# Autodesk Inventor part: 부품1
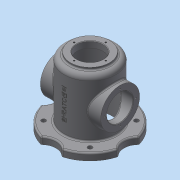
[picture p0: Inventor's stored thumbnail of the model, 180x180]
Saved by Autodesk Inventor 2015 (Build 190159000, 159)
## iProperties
Created: 2022-04
Part Number: 부품1
Material: 일반
Document SubType Name: Modeling
Designer: User
Density: 1 g/cm^3
Appearance: 기본값
Author: User
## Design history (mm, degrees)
sketch "스케치1"
  geometry: C1 r 82 at (0, 0); 1 further point
  constraints: 1 centre point, 1 coincident
  dimensions: "d0" = 164 diameter of C1
extrude "돌출1" new body sketch "스케치1" distance "d1" = 14; taper "d2" = 0 deg
sketch "스케치2"
  geometry: C1 r 30 at (-100, 0); 1 further point
  constraints: 1 centre point, 1 horizontal alignment
  dimensions: "d3" = 60 diameter of C1; "d4" = 100 distance of point (0, 0) C1.centre
extrude "돌출2" cut sketch "스케치2" stored distance "d5" = 14; taper "d6" = 0 deg
sketch "스케치3"
  geometry: L1 (-67.5, 0)-(0, 0); L2 (0, 0)-(-47.73, 47.73); L3 (0, 0)-(0, 67.5); C1 r 4.5 at (-47.73, 47.73); A1 r 67.5 centre (0, 0) between (-67.5, 0) and (-47.73, 47.73); 1 further point
  constraints: 6 end point, 3 point on circle, 2 centre point, 2 coincident, 1 horizontal, 1 perpendicular
  dimensions: "d10" = 135 diameter of A1; "d11" = 45 deg angle of L2 L1; "d12" = 9 diameter of C1
extrude "돌출3" cut sketch "스케치3" stored distance "d13" = 14; taper "d14" = 0 deg
sketch "스케치4"
  geometry: C1 r 53 at (0, 0); 1 further point
  constraints: 1 centre point, 1 coincident
  dimensions: "d18" = 106 diameter of C1
extrude "돌출4" join sketch "스케치4" distance "d19" = 118; taper "d20" = 0 deg
sketch "스케치5"
  geometry: C1 r 40 at (0, 0); 1 further point
  constraints: 1 centre point, 1 coincident
  dimensions: "d21" = 80 diameter of C1
extrude "돌출5" join sketch "스케치5" distance "d22" = 5; taper "d23" = 0 deg
sketch "스케치6"
  geometry: C1 r 27 at (0, 0); 1 further point
  constraints: 1 centre point, 1 coincident
  dimensions: "d24" = 54 diameter of C1
extrude "돌출6" cut sketch "스케치6" stored distance "d25" = 5; taper "d26" = 0 deg
sketch "스케치7"
  geometry: C1 r 45 at (0, 0); 1 further point
  constraints: 1 centre point, 1 coincident
  dimensions: "d27" = 90 diameter of C1
extrude "돌출7" cut sketch "스케치7" distance "d28" = 124; taper "d29" = 0 deg
sketch "스케치8" dims "d30" = 65
  geometry: 3 further points
  constraints: 2 vertical alignment, 1 coincident, 2 other
hole "구멍1" sketch "스케치8" at (0, 32.5) diameter "d31" = 3.242; stored, may be unused: countersink angle "d35" = 90 deg, drill point angle "d37" = 118 deg; dims "d32" = 8, "d33" = 4, "d34" = 2, "d36" = 10
node "작업 평면1"
sketch "스케치9"
  geometry: L1 (21.541, 0)-(-21.541, 0) reference; L2 (21.541, 0)-(79.12, 0) reference; C1 r 40 at (0, 68); 2 further points
  constraints: 1 centre point, 1 midpoint, 1 vertical alignment
  dimensions: "d42" = 80 diameter of C1; "d43" = 68 distance from line of L2 C1.centre
extrude "돌출8" join sketch "스케치9" stored distance "d44" = 124; taper "d45" = 0 deg
sketch "스케치10" dims "d46" = 65
  geometry: 3 further points
  constraints: 2 vertical alignment, 2 other
hole "구멍2" sketch "스케치10" at (0, 32.5) diameter "d47" = 3.242; stored, may be unused: countersink angle "d51" = 90 deg, drill point angle "d53" = 118 deg; dims "d48" = 8, "d49" = 4, "d50" = 2, "d52" = 10
node "작업 평면2"
sketch "스케치11"
  geometry: L1 (-68, -21.541)-(-68, 21.541) reference; C1 r 27 at (0, 0); 2 further points
  constraints: 1 centre point, 1 horizontal alignment, 1 midpoint
  dimensions: "d58" = 54 diameter of C1; "d59" = 68 distance from line of L1 C1.centre
extrude "돌출9" cut sketch "스케치11" stored distance "d60" = 124; taper "d61" = 0 deg
fillet "모깎기1" dims "d62" = 3
fillet "모깎기2" dims "d63" = 3
fillet "모깎기3" dims "d64" = 3
fillet "모깎기4" dims "d65" = 3
fillet "모깎기5" dims "d66" = 10
node "작업 평면3"
node "작업 평면4"
sketch "스케치12"
  geometry: 2 further points
  constraints: 1 vertical alignment, 1 other
  dimensions: "d69" = 70 distance of point (0, 70) point (0, 0)
feature "엠보싱1" sketch "스케치12" dims "d70" = 0.5, "d71" = 0
fillet "모깎기6" dims "d72" = 3
chamfer "모따기1" distance "d73" = 1; stored, may be unused: second distance "d74" = 2, angle "d75" = 45 deg
node "솔리드1"
pattern_circular "원형 패턴1" dims angle "d8" = 360 deg
pattern_circular "원형 패턴2" dims angle "d16" = 360 deg
pattern_circular "원형 패턴3" dims angle "d39" = 360 deg
pattern_circular "원형 패턴4" dims angle "d55" = 360 deg
mirror "대칭1"
other parameters: "d41" = 62, "d57" = 0, "d67" = -185, "d68" = 16.75
